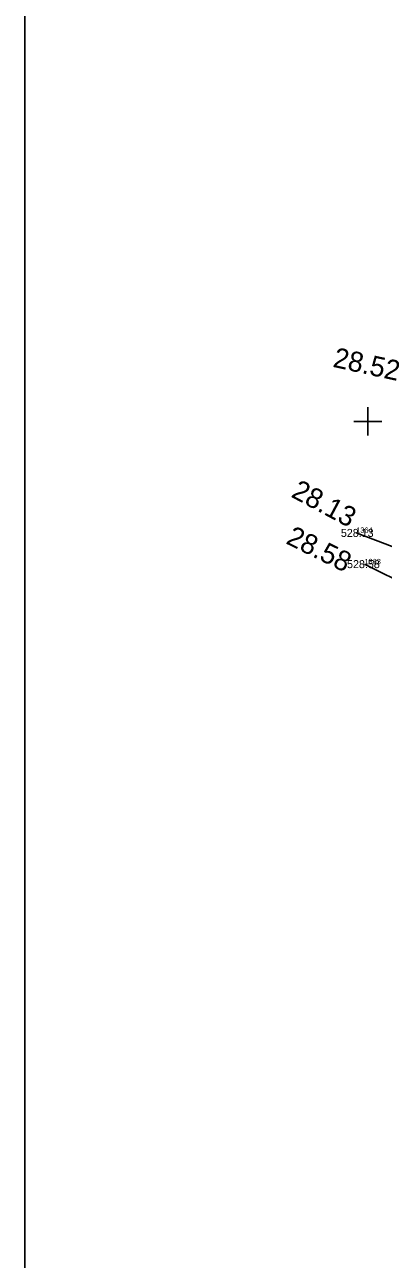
# Model space of a CAD drawing. Extents: x -866693 to -866303, y -1041966 to -1040244.
# Drawn here: x -866512.87 to -866499.42, y -1041781.41 to -1041735.13 of the extents above; entities that cross this region are included whole.
import ezdxf

# ---------------------------------------------------------------- set-up
doc = ezdxf.new("R2010")
doc.units = 0
for name, color, linetype in [('12 potok _kanál-břeh', 7, 'Continuous'), ('13 potok _kanál-dno', 7, 'Continuous'), ('Bod', 7, 'Continuous'), ('Formát', 7, 'Continuous'), ('Nadmořská výška', 7, 'Continuous'), ('Nadmořská výška_tisk', 7, 'Continuous'), ('Síť křížek', 7, 'Continuous'), ('Číslo bodu', 7, 'Continuous')]:
    doc.layers.add(name, color=color, linetype=linetype)

msp = doc.modelspace()

# ---------------------------------------------------------------- linework, layer by layer
at = {"layer": '12 potok _kanál-břeh'}
msp.add_line((-866500.125, -1041755.353), (-866494.011, -1041758.378), dxfattribs=at)
at = {"layer": '13 potok _kanál-dno'}
msp.add_line((-866492.83, -1041757.067), (-866500.436, -1041754.175), dxfattribs=at)
at = {"layer": 'Bod'}
for p, q in [((-866500.436, -1041754.175), (-866500.436, -1041754.175)), ((-866500.125, -1041755.353), (-866500.125, -1041755.353))]:
    msp.add_line(p, q, dxfattribs=at)
at = {"layer": 'Formát'}
msp.add_lwpolyline([(-866512.871, -1041669.147), (-866302.871, -1041669.147), (-866302.871, -1041966.147), (-866512.871, -1041966.147)], close=True, dxfattribs=at)
at = {"layer": 'Síť křížek'}
for p, q in [((-866500, -1041750.53), (-866500, -1041749.47)), ((-866500.53, -1041750), (-866499.47, -1041750))]:
    msp.add_line(p, q, dxfattribs=at)

# ---------------------------------------------------------------- texts
at = {"layer": 'Nadmořská výška'}
for s, p in [('528.13', (-866501.011, -1041754.33)), ('528.58', (-866500.78, -1041755.5))]:
    msp.add_text(s, height=0.3, dxfattribs=at).set_placement(p)
at = {"layer": 'Nadmořská výška_tisk'}
for s, rotation, p in [('28.52', 347.649, (-866501.342, -1041747.949)), ('28.13', 331.9166, (-866502.914, -1041752.812)), ('28.58', 333.7153, (-866503.11, -1041754.56))]:
    msp.add_text(s, height=0.75, rotation=rotation, dxfattribs=at).set_placement(p)
at = {"layer": 'Číslo bodu'}
for s, p in [('1364', (-866500.436, -1041754.175)), ('1363', (-866500.125, -1041755.353))]:
    msp.add_text(s, height=0.2, dxfattribs=at).set_placement(p)

doc.saveas('drawing.dxf')
